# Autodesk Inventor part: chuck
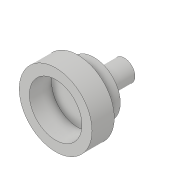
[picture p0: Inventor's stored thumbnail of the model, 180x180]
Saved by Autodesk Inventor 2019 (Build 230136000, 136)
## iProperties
Created: 2019-10
Part Number: chuck
Material: Generic
Document SubType Name: Modeling
Designer: hp
Density: 1 g/cm^3
Appearance: Default
Author: hp
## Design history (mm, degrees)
sketch "Sketch1"
  geometry: C1 r 18 at (0, 0); C2 r 13 at (0, 0); 1 further point
  constraints: 2 centre point, 2 coincident
  dimensions: "d0" = 36 diameter of C1; "d1" = 26 diameter of C2
extrude "Extrusion1" new body sketch "Sketch1" distance "d2" = 11; taper "d3" = 0 deg
sketch "Sketch2"
  geometry: C1 r 13 at (0, 0); 1 further point
  constraints: 1 centre point, 1 coincident
extrude "Extrusion2" join sketch "Sketch2" distance "d4" = 8; taper "d5" = 0 deg
sketch "Sketch3"
  geometry: C1 r 5.243 at (0, 0); 1 further point
  constraints: 1 centre point, 1 coincident
extrude "Extrusion3" join sketch "Sketch3" distance "d6" = 15; taper "d7" = 0 deg
body "Solid1"
